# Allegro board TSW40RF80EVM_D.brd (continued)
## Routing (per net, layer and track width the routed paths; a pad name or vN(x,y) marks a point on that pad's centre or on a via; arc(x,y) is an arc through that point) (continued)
Net_259:
  vias: v1(148.69,18.54)
Net_261:
  vias: v1(148.69,14.73)
Net_262:
  vias: v1(148.69,13.46)
Net_263:
  vias: v1(148.69,10.92)
Net_267:
  vias: v1(147.42,38.86)
Net_268:
  vias: v1(147.42,57.91)
Net_271:
  vias: v1(147.42,28.7)
Net_273:
  vias: v1(147.42,24.89)
Net_275:
  vias: v1(147.42,21.08)
Net_276:
  vias: v1(147.42,19.81)
Net_278:
  vias: v1(147.42,16)
Net_279:
  vias: v1(147.42,13.46)
Net_282:
  vias: v1(147.42,9.65)
Net_297:
  vias: v1(146.15,21.08)
Net_298:
  vias: v1(146.15,18.54)
Net_300:
  vias: v1(146.15,14.73)
Net_301:
  vias: v1(146.15,13.46)
Net_315:
  vias: v1(144.88,16)
Net_318:
  vias: v1(144.88,9.65)
Net_350:
  vias: v1(142.34,35.05)
Net_361:
  vias: v1(142.34,13.46)
Net_362:
  vias: v1(142.34,12.19)
OSCI: length 5.5
  BOTTOM w0.305: U10.2 104.84,48.65 105.28,49.1 105.28,50.27 v1(107.04,52.02)
OSCINN: length 9.1
  BOTTOM w0.203: C228.2 46.62,35.23 C229.2 45.83,35.41 45.12,35.41 44.65,35.87 44.65,38.11 43.05,39.7 41.7,39.7 41.63,39.63 U7.44
OSCINP: length 9
  BOTTOM w0.203: U7.43 41.63,40.13 41.7,40.06 43.2,40.06 45.01,38.25 45.01,36.02 45.26,35.76 45.88,35.76 C223.2 46.62,35.89 C221.2
OSCN: length 1.9
  BOTTOM w0.381: C227.2 49.1,35.23 R112.2 R116.1 47.86,35.25 C228.1
OSCO: length 5.5
  BOTTOM w0.305: v1(107.85,49.79) 107.85,48.77 107.54,48.46 105.71,48.46 105.41,48.16 U10.3
OSCOUTN: length 5.3
  BOTTOM w0.203: U7.41 41.63,41.13 41.7,41.21 43.8,41.21 44.04,41.45 45.09,41.45 R121.1 45.85,41.3 C231.1
OSCOUTP: length 5.3
  BOTTOM w0.203: C230.1 45.85,41.96 R120.1 45.09,41.81 43.9,41.81 43.65,41.56 41.7,41.56 41.63,41.63 U7.40
OSCP: length 1.9
  BOTTOM w0.381: C221.1 47.86,35.86 R109.1 R104.2 49.1,35.89 C220.2
PDN: length 42.4
  TOP w0.127: JP4.2 65.49,37.2 v1(51.6,37.2) ; v1(45.8,50.8) 45.29,51.31 38.86,51.31 38.29,51.88 U2.50
  L4_SIG w0.127: v1(45.8,50.8) 45.8,49.85 48.33,47.32 48.51,47.32 52.43,43.4 52.43,38.02 v1(51.6,37.2)
PG_C2M: length 7.4
  L6_SIG w0.127: v1(155.68,57.28) 155.68,57.91 153.8,59.79 150.57,59.79 v1(149.96,59.18)
PG_M2C: length 9.4
  L6_SIG w0.127: v1(155.68,61.09) 155.27,61.49 150.83,61.49 149.22,59.89 148.03,59.89 147.42,59.28 v1(147.42,59.18)
PLL2 LOCKED: length 1.1
  TOP w0.127: R127.1 47.32,39.78 D5.1
PRSNT_M2C_L: length 17
  L4_SIG w0.127: v2(144.35,57.33) 145.29,58.27 145.29,58.32 145.57,58.6 149.91,58.6 155.68,52.83 v1(155.68,50.93)
  BOTTOM w0.102: J14.H2 144.88,57.86 v2(144.35,57.33)
RES0: length 4.5
  L8_SIG w0.127: v1(152.5,9.65) v1(155.68,6.48)
RX0N: length 13.4
  TOP w0.203: U1.M4 20.47,29.05 20.47,30.08 20.73,30.33 20.98,30.33 21.1,30.22 21.35,30.22 21.53,30.39 21.53,30.65 21.41,30.76 21.41,31.02 22.07,31.67 31.17,31.67 C18.2
RX0P: length 13.4
  TOP w0.203: U1.M5 20.12,29.14 20.12,30.23 21.92,32.03 31.17,32.03 C19.2
RX1N: length 10.8
  TOP w0.203: U1.M3 21.67,29.08 21.67,29.59 22.48,30.4 31.17,30.4 C22.2
RX1P: length 10.8
  TOP w0.203: U1.M2 22.02,29.11 22.02,29.44 22.63,30.05 22.9,30.05 23.08,29.87 23.08,29.72 23.25,29.54 23.51,29.54 23.68,29.72 23.68,29.87 23.86,30.05 31.17,30.05 C20.2
RX2N: length 8.4
  TOP w0.203: C23.2 31.17,28.42 26.89,28.42 26.77,28.3 23.28,28.3 U1.L1
RX2P: length 8.4
  TOP w0.203: U1.M1 23.28,28.65 26.62,28.65 26.75,28.78 31.17,28.78 C21.2
RX3N: length 8.5
  TOP w0.203: U1.K1 23.3,27.03 27.13,27.03 27.3,27.2 31.17,27.2 C24.2
RX3P: length 8.4
  TOP w0.203: C25.2 31.17,26.85 27.45,26.85 27.27,26.67 23.25,26.67 U1.J1
RX4N: length 8.4
  TOP w0.203: C15.2 31.17,23.95 27.41,23.95 27.3,23.85 23.28,23.85 U1.F1
RX4P: length 8.4
  TOP w0.203: U1.E1 23.28,23.5 27.45,23.5 27.55,23.6 31.17,23.6 C14.2
RX5N: length 8.4
  TOP w0.203: U1.B1 23.25,20.68 31.14,20.68 C10.2
RX5P: length 8.4
  TOP w0.203: C11.2 31.19,20.32 23.3,20.32 U1.A1
RX6N: length 8.4
  TOP w0.203: U1.C1 23.28,21.89 28.29,21.89 28.37,21.97 31.17,21.97 C12.2
RX6P: length 8.4
  TOP w0.203: U1.D1 23.28,22.25 28.14,22.25 28.22,22.33 31.17,22.33 C13.2
RX7N: length 8.4
  TOP w0.203: U1.G1 23.28,25.1 29.31,25.1 29.41,25.2 31.19,25.2 C17.2
RX7P: length 8.4
  TOP w0.203: C16.2 31.14,25.55 29.26,25.55 29.16,25.45 23.28,25.45 U1.H1
SCAN_EN: length 0.1
  BOTTOM w0.203: v3(37.79,53.65) 37.8,53.65 R50.2
SCL: length 16.1
  L6_SIG w0.127: v1(155.68,35.69) 155.68,33.83 155.22,33.38 155.22,26.97 151.41,23.16 150.67,23.16 v2(150.62,23.11)
  BOTTOM w0.102: J14.C30 150.62,22.96 v2(150.62,23.11)
SCLK: length 60.4
  L8_SIG w0.102: 15.47,29.22 15.47,28.7 15.7,28.47 16.25,28.47 v1(16.65,28.07)
  L8_SIG w0.127: v1(68.76,37.41) 68.73,37.67 67.46,38.94 43.33,38.94 41.99,37.59 29.51,37.59 26.92,35 26.59,35 24.82,33.22 18.77,33.22 15.47,29.92 15.47,29.22
SDA: length 9.7
  L8_SIG w0.127: v1(155.68,28.7) 155.68,25.7 152.17,22.2 151.69,22.2 151.23,21.74 v1(151.23,21.08)
SDCLKOUT3N: length 3.2
  BOTTOM w0.203: R75.1 29.31,43.79 R80.1 29.34,43.81 29.51,43.64 29.87,43.64 30.29,44.06 30.73,44.06 30.8,44.14 U7.14
SDCLKOUT3P: length 3.2
  BOTTOM w0.203: R74.1 29.31,43.18 R79.1 29.46,43.28 30.01,43.28 30.44,43.71 30.73,43.71 30.8,43.63 U7.13
SDCLKOUT5N: length 3.4
  BOTTOM w0.203: U7.23 35.46,46.8 35.39,46.87 35.39,47.36 35.08,47.67 35.08,48.22 R101.1 35.22,49.09 R99.1
SDCLKOUT5P: length 3.4
  BOTTOM w0.203: R96.1 34.53,49.1 R100.1 34.72,48.15 34.72,47.52 35.03,47.21 35.03,46.87 34.96,46.8 U7.22
SDENB: length 55.1
  L8_SIG w0.102: 17.81,29.22 17.47,28.87 v1(17.45,28.87)
  L8_SIG w0.127: v1(68.73,34.14) 67.44,32.84 66.4,32.84 65.41,33.83 41.23,33.83 41.17,33.9 37.59,33.9 37.52,33.83 35.23,33.83 34.32,34.75 33.4,34.75 30.3,31.65 24.97,31.65 23.27,29.95 18.97,29.95 18.44,29.41 18.01,29.41 17.81,29.22
SDIO: length 57.4
  L8_SIG w0.102: 15.85,29.22 v1(15.85,28.87)
  L8_SIG w0.127: v1(68.76,36.32) 68.22,36.86 59.16,36.86 58.22,35.92 45.19,35.92 44.98,36.12 37.52,36.12 36.83,36.8 33.32,36.8 32.61,36.09 32.41,36.09 28.98,32.66 19.25,32.66 15.85,29.27 15.85,29.22
SDO: length 56.2
  L8_SIG w0.102: 17,29.22 v1(16.65,28.87)
  L8_SIG w0.127: 17,29.22 17.64,29.86 18.09,29.86 18.64,30.4 22.71,30.4 24.49,32.18 29.26,32.18 31.94,34.86 32.73,34.86 33.17,35.31 34.32,35.31 35.38,34.24 37.85,34.24 38.94,35.33 59.33,35.33 59.54,35.53 61.7,35.53 62,35.23 65.81,35.23 66.22,34.82 68.3,34.82 v1(68.73,35.26)
SLEEP: length 93.9
  L6_SIG w0.127: JP1.2 73.84,12.57 72.14,10.87 57.61,10.87 57.15,10.41 38,10.41 37.72,10.13 23.6,10.13 21.82,11.91 17.81,11.91 14.02,15.7 13.06,15.7 9.47,19.28 9.47,28.25 11.76,30.53 v1(11.76,30.78)
  BOTTOM w0.102: 17.07,29.22 17.07,28.4 17.39,28.07 v1(17.45,28.07)
  BOTTOM w0.127: v1(11.76,30.78) 15.88,30.78 17.07,29.59 17.07,29.22
STAT 0: length 1.1
  TOP w0.127: R124.1 D2.1
STAT 1: length 1.1
  TOP w0.127: R125.1 D3.1
SYNC: length 1.1
  TOP w0.305: v3(31.27,40.13) v3(31.96,40.13)
  BOTTOM w0.305: U7.6 v3(31.27,40.13)
SYSREF-N: length 3.5
  TOP w0.203: U1.A4 20.88,19.85 20.88,16.86 R17.2
SYSREF-P: length 3.5
  TOP w0.203: U1.A3 21.23,19.85 21.23,16.87 R16.2
TCK: length 27.2
  L6_SIG w0.127: v1(149.96,23.62) 150.59,23.62 154.74,27.77 154.74,35.56 155.23,36.06 155.23,41.59 156.13,42.49 156.13,47.29 v1(155.68,47.75)
TDI: length 27.7
  L6_SIG w0.127: v2(149.33,21.59) 148.03,22.89 148.03,27.41 150.6,29.97 150.6,30.18 151.92,31.5 151.92,37.65 152.95,38.68 152.95,39.31 154.56,40.92 154.56,41.76 155.68,42.88 v1(155.68,44.58)
  BOTTOM w0.102: J14.D30 149.96,22.23 v2(149.33,21.59)
TDO: length 24.5
  L6_SIG w0.127: v1(149.96,21.08) 149.99,21.08 150.65,20.42 152.81,20.42 153.14,20.75 153.14,23.42 156.26,26.54 156.26,35.97 155.68,36.55 v1(155.68,40.13)
TMS: length 9.1
  L8_SIG w0.127: v1(149.96,18.54) 150.6,18.54 155.68,23.62 v1(155.68,24.89)
TRST_L: length 7.2
  L8_SIG w0.127: v1(155.68,14.73) 155.02,15.39 151.92,15.39 v2(151.89,15.37)
  BOTTOM w0.102: v2(151.89,15.37) 151.87,15.34 151.21,15.34 150.75,15.8 150.75,16.03 149.96,16.81 J14.D34
TXA0_M: length 5.3
  TOP w0.203: U2.62 41.03,57.71 43.13,57.71 44.55,59.13 45.39,59.13 C111.1
TXA0_P: length 5.2
  TOP w0.203: U2.61 41,57.35 43.28,57.35 44.7,58.78 45.39,58.78 C110.1
TXA1_M: length 5.2
  TOP w0.203: C124.1 45.39,57.51 44.81,57.51 43.52,56.21 41.03,56.21 U2.59
TXA1_P: length 5.2
  TOP w0.203: C123.1 45.39,57.15 44.96,57.15 43.66,55.85 41,55.85 U2.58
TXA2_M: length 5.1
  TOP w0.203: C126.1 45.39,55.88 44.91,55.88 43.77,54.74 41,54.74 U2.56
TXA2_P: length 5.1
  TOP w0.203: U2.55 41.03,54.38 43.92,54.38 45.06,55.52 45.39,55.52 C125.1
TXA3_M: length 7.2
  TOP w0.203: C135.1 45.34,54.13 44.99,54.13 43.62,52.76 42.1,52.76 41.92,52.93 41.92,53.06 41.74,53.24 41.49,53.24 41.31,53.06 41.31,52.93 41.13,52.76 40.54,52.76 40.21,53.09 40.21,53.56 U2.54
TXA3_P: length 7.2
  TOP w0.203: U2.53 39.85,53.59 39.85,52.94 40.39,52.4 43.76,52.4 45.14,53.77 45.44,53.77 C127.1
TXB0_M: length 5.1
  TOP w0.203: C137.1 45.39,60.4 44.07,60.4 43.03,59.36 41.01,59.36 U2.65
TXB0_P: length 5.1
  TOP w0.203: U2.66 41.02,59.72 42.88,59.72 43.92,60.76 45.39,60.76 C136.1
TXB1_M: length 5.1
  TOP w0.203: U2.68 41.03,60.88 42.62,60.88 43.76,62.03 45.39,62.03 C140.1
TXB1_P: length 5.1
  TOP w0.203: C138.1 45.39,62.38 43.61,62.38 42.47,61.24 41,61.24 U2.69
TXB2_M: length 5.2
  TOP w0.203: U2.71 41,62.36 41.6,62.36 42.9,63.65 45.39,63.65 C148.1
TXB2_P: length 5.2
  TOP w0.203: C141.1 45.39,64.01 42.75,64.01 41.45,62.71 41.03,62.71 U2.72
TXB3_M: length 7
  TOP w0.203: U2.1 40.22,63.52 40.22,64 40.58,64.36 40.83,64.36 40.94,64.25 41.19,64.25 41.37,64.43 41.37,64.68 41.26,64.79 41.26,65.04 41.5,65.28 45.39,65.28 C150.1
TXB3_P: length 7
  TOP w0.203: U2.2 39.87,63.52 39.87,64.14 41.36,65.63 45.39,65.63 C149.1
TXENABLE: length 103.2
  L6_SIG w0.127: v1(11.05,31.39) 11.05,31.29 8.94,29.18 8.94,19.15 12.14,15.95 12.14,15.37 15.57,11.94 16.26,11.94 17.35,10.85 20.98,10.85 23.93,7.9 29.69,7.9 30.71,8.92 58.95,8.92 59.89,9.86 62.56,9.86 62.56,9.88 62.84,10.16 63.2,10.16 63.47,9.88 63.47,9.86 73.08,9.86 74.78,11.56 80.37,11.56 JP2.2
  BOTTOM w0.102: v1(19.05,27.27) 19.05,27.35 18.64,27.77 18.64,28.3 18.44,28.5 18.1,28.5 17.88,28.72 17.88,29.22
  BOTTOM w0.127: 17.88,29.22 17.88,29.39 16.1,31.17 13.51,31.17 13.28,31.39 v1(11.05,31.39)
USB_DM: length 45.4
  BOTTOM w0.203: R139.2 135.36,20.73 C267.1 135.38,21.14 135.22,21.3 135.22,24.72 134.34,25.6 133.88,25.6 127.28,32.21 124.84,32.21 115.64,41.4 115.37,41.4 112.65,44.12 109.14,44.12 107.49,45.77 105.66,45.77 105.35,46.08 104.7,46.08 104.62,46.16 U10.7
USB_DP: length 45.4
  BOTTOM w0.203: U10.8 104.56,45.65 104.62,45.72 105.21,45.72 105.51,45.42 107.34,45.42 108.99,43.76 112.5,43.76 115.22,41.05 115.49,41.05 124.69,31.85 127.13,31.85 133.74,25.25 134.19,25.25 134.86,24.57 134.86,24.32 134.68,24.14 134.54,24.14 134.37,23.96 134.37,23.71 134.54,23.53 134.68,23.53 134.86,23.35 134.86,21.3 134.7,21.14 C266.1 134.72,20.73 R142.2
USB_EECLK: length 5.1
  TOP w0.127: R156.1 100.77,51.8 v3(100.77,51.03) 100.77,49.66 99.52,48.42 U12.2
USB_EECS: length 5
  TOP w0.127: v3(101.27,51.88) 101.27,51.87 101.27,49.56 100.17,48.46 U12.1
USB_REF:
  vias: v3(102.79,46.65)
USB_RST:
  vias: v3(104.5,42.66)
VCM: length 17.9
  TOP w0.203: v1(30.53,61.32) 30.55,61.3 U2.22
  L4_SIG w0.203: v1(30.53,61.32) 30.53,61.85 29.46,62.92 26.95,62.92 26.62,62.59 16.74,62.59 v1(16.59,62.43)
  BOTTOM w0.305: TP5.1 14.61,62.43 v1(16.59,62.43)
VIO_B_M2C: length 17.8
  L8_SIG w0.127: v1(143.61,10.92) v1(142.34,9.65) 142.37,9.65 143.41,8.61 150.37,8.61 v1(155.68,3.3)
VREF_A_M2C: length 13.3
  L4_SIG w0.127: v1(155.68,54.1) 150.14,59.64 145.34,59.64 v1(144.88,59.18)
VREF_B_M2C: length 16.2
  L6_SIG w0.127: v1(144.27,59.74) 144.22,59.79 144.22,60.5 147.6,63.88 155.3,63.88 v1(155.68,64.26)
  BOTTOM w0.102: 142.72,59.56 J14.K1
  BOTTOM w0.127: v1(144.27,59.74) 144.02,59.99 143.15,59.99 142.72,59.56
Y2_N: length 4.8
  BOTTOM w0.381: Y1.4 53.26,34.32 52.35,35.23 R114.1 51.03,35.23 R113.1
Y2_P: length 4.8
  BOTTOM w0.381: R107.1 51.03,35.89 R108.1 52.27,35.89 53.24,36.86 Y1.5
YO2_N: length 0.7
  BOTTOM w0.381: C227.1 R113.2
YO2_P: length 0.7
  BOTTOM w0.381: R107.2 C220.1
N16791764: length 3.1
  BOTTOM w0.254: R138.1 133.43,18.59 J15.1
N16791900:
  vias: v3(102.89,47.64) v3(103.64,47.65) v3(104.46,47.66)
N16791904: length 1.7
  TOP w0.305: v3(104.52,45.15) 103.63,45.15 C247.1 ; C247.1 103.55,45.18 102.92,45.18 C248.1 ; C247.1 103.59,45.2 v3(103.64,45.16)
  vias: v3(102.87,45.15)
N16792068: length 1.3
  TOP w0.127: R151.2 R146.2 R150.1
N16792392: length 2.3
  TOP w0.127: R157.1 98.24,49.43 R159.2 98.22,48.94 U12.4
N17033323:
  vias: v1(106.09,46.42)
N17033325: length 0.4
  BOTTOM w0.305: v1(107.46,46.43) 107.44,46.42 R137.2
N17828171: length 5.5
  BOTTOM w0.305: v1(111.35,47.9) 111.35,48.83 v1(111.36,48.83)
  BOTTOM w0.508: FB13.1 113.87,50.26 113.41,49.81 111.96,49.81 111.36,49.21 v1(111.36,48.83)
N17829143: length 1.1
  BOTTOM w0.305: R136.1 112.73,45.68 v1(113.28,46.24)
N17906763: length 4.7
  TOP w0.381: J13.1 28.35,43.51 28.73,43.13 28.73,41.66 R123.1
N18864728: length 0.4
  TOP w0.127: Q2.1 138.91,41.53 v1(138.89,41.5)
N18864763: length 12.6
  BOTTOM w0.102: 141.86,40.61 146.35,40.61 146.63,40.34 146.63,40.23 147.4,39.47 147.52,39.47 148.13,38.86 148.13,38.56 148.44,38.25 149.35,38.25 J14.D17
  BOTTOM w0.127: R132.1 141.07,40.49 141.2,40.61 141.86,40.61
N18864775: length 12.9
  TOP w0.127: v1(138.89,33.17) 139.06,33.35 142.77,33.35 146.18,36.75 149.1,36.75 v1(149.28,36.93)
  BOTTOM w0.102: v1(149.28,36.93) 149.3,36.93 J14.D18
N18864798: length 0.9
  TOP w0.127: v1(138.96,42.49) 139.29,42.82 Q2.3
N18865554:
  vias: v1(137.97,42.44)
N19080738:
  vias: v1(53.77,40.06) v1(54.48,40.21) v1(55.12,40.21) v1(55.75,40.21) v1(56.39,40.21)
N19081029:
  vias: v1(60.4,36.09)
N19083254: length 8.8
  TOP w0.127: R126.2 45.21,44.73 42.16,47.78 40.51,47.78 v1(39.47,46.74)
  BOTTOM w0.127: U7.31 39.47,46.73 v1(39.47,46.74)
N19083268: length 8.3
  TOP w0.127: v1(41.78,37.03) 41.78,36.53 42.21,36.09 43.97,36.09 44.4,36.53 44.4,38.94 R127.2
  BOTTOM w0.127: v1(41.78,37.03) 41.19,37.63 U7.48
N19083286: length 13.8
  TOP w0.127: v1(34.95,35.31) 35.41,35.31 36.12,36.02 36.12,36.22 37.41,37.52 38.28,37.52 40.39,35.41 45.14,35.41 R125.2
  BOTTOM w0.127: U7.59 34.96,35.32 v1(34.95,35.31)
N19083328: length 15.3
  TOP w0.127: v1(35.46,35.99) 35.46,36.58 36.7,37.82 36.7,38.18 37.15,38.63 38.48,38.63 38.73,38.38 38.73,37.62 40.59,35.76 44.37,35.76 45.21,36.6 45.21,37.62 R124.2
  BOTTOM w0.127: U7.58 35.46,36 v1(35.46,35.99)
N19083344: length 0.3
  BOTTOM w0.305: U7.12 31.97,43.13 v3(31.98,43.13)
N19083346: length 0.5
  BOTTOM w0.305: v3(31.14,42.65) 31.15,42.63 U7.11
N19083364: length 1.5
  TOP w0.305: v3(31.63,42.13) 31.65,42.11 C232.2
  BOTTOM w0.305: v3(31.98,42.14) 31.97,42.13 v3(31.63,42.13) ; v3(40.44,45.13) 40.44,45.14 U7.33 41.12,45.14 v3(41.22,45.24)
  vias: v3(40.44,43.64)
N19083444: length 1.6
  TOP w0.305: FB7.2 40.48,42.11 v3(40.46,42.13) v3(41.12,42.13)
  BOTTOM w0.305: U7.39 v3(40.46,42.13)
N19083446: length 0.6
  TOP w0.305: FB9.2 40.47,39.14 v3(40.46,39.13)
  vias: v3(41.12,39.14)
N19083508: length 4.4
  TOP w0.305: 42.04,39.14 42.04,39.09 v3(41.07,38.13) v3(40.46,38.13) ; v1(41.81,38.13) 42.04,38.13 42.65,38.73 FB6.2
  BOTTOM w0.305: v1(41.81,38.13) 41.8,38.13 U7.47
N19083566: length 1.4
  TOP w0.305: v3(34.47,45.62) 34.47,46.29 v3(34.46,46.29) ; C236.2 FB3.2
N19083568: length 1.4
  TOP w0.305: v3(32.46,45.63) 32.46,46.3 v3(32.46,46.3) ; C235.2 FB5.2
N19083616: length 4.5
  TOP w0.305: 32.46,37.11 v4(32.46,36.45) ; 32.46,37.11 v4(32.46,37.13) 32.03,36.32 ; 32.46,37.11 32.09,36.74 ; v4(32.46,36.45) 32.46,36.35 C244.2 32.09,36.66 32.09,36.74 ; v4(32.46,36.45) 32.33,36.32 ; 32.09,36.74 31.67,36.32
  TOP w0.508: FB11.2 31.67,36.32 C244.2
N19083618: length 1.1
  TOP w0.305: C243.2 FB10.2
  BOTTOM w0.305: U7.53 v3(37.96,37.13)
  vias: v3(37.96,36.47)
N19083707: length 1.6
  TOP w0.305: FB4.2 37.03,46.29 ; 37.03,46.29 v3(36.96,46.29) 36.96,45.71 C237.2 ; 37.03,46.29 C237.2 ; C237.2 v3(36.96,45.64)
N19234861: length 0.6
  TOP w0.305: v3(40.46,40.63) 40.48,40.61 FB8.2
  vias: v3(41.12,40.64)
N19402254: length 1.6
  L4_SIG w0.102: v3(96.95,49.56) 96.77,49.74 v3(96.77,51.03)
N19402263: length 1.5
  L4_SIG w0.102: v3(96.27,51.03) 96.27,49.63 v3(96.19,49.56)
N19402272: length 1.6
  L4_SIG w0.102: v3(95.77,51.03) 95.77,49.84 v3(95.48,49.56)
N19402281: length 0.9
  BOTTOM w0.127: U10.48 93.22,49.16 v3(93.24,49.17)
N19909006: length 1.5
  TOP w0.305: C290.2 91.22,14.7 U17.8
N20060120: length 3.2
  TOP w0.203: C9.1 18.82,17.2 18.82,19.84 U1.A6
N20060672: length 3.2
  TOP w0.203: U1.A7 18.49,19.84 18.49,17.22 C7.1
N20072726: length 1.9
  TOP w0.305: C427.1 R228.2 28.37,59.37 28.07,59.67 U3.6
N20072730: length 2
  TOP w0.305: U4.6 28.07,57.34 28.37,57.64 R228.1 C428.1
N20074990: length 2.6
  TOP w0.381: C166.2 18.45,64.14 T6.4 R57.1
N20074992: length 3.5
  TOP w0.381: R56.1 T6.6 18.45,66.93 C165.2 C164.2
N20075215: length 2.6
  TOP w0.381: R54.1 T4.6 18.45,52.96 C159.2
N20075219: length 3.4
  TOP w0.381: R55.1 T4.4 18.43,50.14 C161.2 C160.2
N20076572: length 1.1
  TOP w0.127: R64.1 D1.1
N20076618:
  vias: v3(71.07,51.05) v3(71.07,50.34)
N20076637: length 0.9
  TOP w0.305: v3(72,47.43) 72.09,47.51 C188.2 U5.36 v3(72.64,47.43)
N20076686: length 0.3
  TOP w0.305: C191.2 72.36,48.95 v3(72.39,48.92)
  vias: v3(72.01,48.92)
N20076744: length 2.6
  BOTTOM w0.203: U5.23 68,50.77 68,52.31 R58.1 68.19,53.11 C170.1
N20076746: length 2.5
  BOTTOM w0.203: U5.22 67.67,50.81 67.67,52.37 R59.1 67.56,52.53 C171.1
N20076858:
  vias: v3(67.06,44.3)
N20076866: length 4.9
  BOTTOM w0.203: C181.1 63.24,51.05 R61.1 63.42,51.01 64.03,50.4 64.03,49.96 65,48.99 65.53,48.99 65.53,49 66.22,49 U5.18
N20076868: length 4.6
  BOTTOM w0.203: C184.1 63.67,51.48 R62.1 63.7,51.23 64.39,50.55 64.39,50.11 65.15,49.35 65.15,49.35 66.21,49.35 U5.19
N20076920: length 0.6
  BOTTOM w0.305: C193.2 R70.1
N20076959: length 1.2
  BOTTOM w0.305: R69.1 C194.1 R68.2
N20076978: length 1.9
  BOTTOM w0.305: R69.2 72.34,47.93 U5.35 72.77,47.93 v3(72.8,47.9)
N20077010: length 0.3
  BOTTOM w0.305: U5.30 71.78,50.7 v3(71.84,50.63)
N20077268: length 0.7
  BOTTOM w0.305: v3(70.08,50.37) 70.06,50.39 U5.27 70.06,51.05 v3(70.05,51.05)
N20077503: length 8
  L6_SIG w0.127: v3(66.29,49.93) 66.81,49.4 67.23,49.4 68.02,50.19 69.14,50.19 69.31,50.03 70.22,50.03 70.89,50.7 71.3,50.7 71.58,50.98 72.62,50.98 v1(73.1,50.5)
N20087628: length 5
  L6_SIG w0.102: 13.92,22.07 16.25,22.07 v3(16.65,21.67)
  L6_SIG w0.127: 13.92,22.07 13.41,22.07 v3(12.27,20.93)
N20088284: length 1.7
  TOP w0.381: R23.2 R24.1 10.84,21.99 11.43,22.58
N20088327: length 1.7
  TOP w0.381: R20.2 R21.1 C26.2
N20098160:
  vias: v3(103.87,41.65)
N20098174: length 1.6
  TOP w0.305: U31.19 89.71,38.58 R326.2
  vias: v3(88.32,38.58)
N20098233:
  vias: v3(101.77,40.62)
N20098235:
  vias: v3(101.27,39.78)
N20098237:
  vias: v3(100.76,38.96)
N20101383: length 7.6
  L6_SIG w0.127: v3(95.76,41.24) 95.76,41.35 93.95,43.16 v3(88.99,43.16)
N20101387: length 9.6
  L10_PWR_SIG w0.102: v3(96.26,38.32) 96.26,38.36 95.05,39.57 95.05,39.9 91.9,43.05 89.38,43.05 v3(88.99,42.66)
N20101391: length 8.4
  L6_SIG w0.127: v3(96.75,41.26) 96.43,40.94 93.65,40.94 92.43,42.16 v3(88.99,42.16)
N20101395: length 10.7
  L10_PWR_SIG w0.102: v3(88.11,41.07) 91.03,41.07 92.91,39.19 93.47,39.19 94.82,37.85 96.81,37.85 v3(97.28,38.32)
N20101461: length 3.6
  BOTTOM w0.127: U11.12 89.61,45.16 90.1,45.65 U10.41
N20101463: length 3.6
  BOTTOM w0.127: U10.40 90.47,45.16 89.99,44.68 89,44.68 U11.13
N20101465: length 3.6
  BOTTOM w0.127: U10.39 90.58,44.65 90.08,44.16 U11.14
N20101467: length 3.6
  BOTTOM w0.127: U11.15 90.37,43.66 90.87,44.16 U10.38
N20101487:
  vias: v3(94.28,38.93)
N20101489:
  vias: v3(95.27,38.93)
N20101501:
  vias: v3(96.75,40.66)
N20101503:
  vias: v3(95.76,40.63)
N20101505:
  vias: v3(97.28,38.93)
N20101507:
  vias: v3(96.26,38.93)
N20119510: length 1.7
  BOTTOM w0.305: U15.7 44.19,5.2 44.69,5.7 C282.1
N20119513: length 1.9
  BOTTOM w0.305: C282.2 45.71,5.78 45.72,5.77 U15.8
N20119835: length 1.7
  BOTTOM w0.305: C283.1 43.69,1.73 U15.3
N20120157: length 2.9
  BOTTOM w0.305: R161.1 R163.1 42.16,6.07 42.16,5.97 43.19,4.94 U15.5
N20121909: length 2.8
  TOP w0.305: R169.1 v1(92.86,13.44) R168.1
  BOTTOM w0.305: v1(92.6,15.35) 92.6,14.28 92.86,14.02 v1(92.86,13.44)
N20122091: length 2
  TOP w0.305: R339.1 R338.1 94.84,14.66 U17.1
  vias: v1(94.79,14.66)
N20123661: length 1.5
  BOTTOM w0.127: R362.2 86.41,10.9 C294.2
N20123671: length 3.3
  L8_SIG w0.305: v1(90.14,11.51) 90.63,11.02 90.81,11.02 91.29,10.54 91.29,9.57 v1(90.74,9.02)
N20123702: length 4.1
  TOP w0.305: v1(88.54,9.67) 88.54,10.56 88.93,10.95 88.93,12.22 v1(89.23,12.52)
  BOTTOM w0.305: v1(89.23,12.52) R171.1
N20123718: length 4.8
  TOP w0.305: v1(90.74,10.32) 90.54,10.32 89.56,11.3 89.56,11.79 90.3,12.52 v1(91.06,12.52)
  BOTTOM w0.305: R336.1 v1(91.06,12.52)
N20149572: length 7.8
  L4_SIG w0.127: v3(98.27,51.03) 98.27,46.9 96.55,45.19 95.83,45.19 v3(95.48,45.54)
N20149573: length 4.5
  L4_SIG w0.127: v3(93.24,52.27) 96.02,52.27 v3(97.27,51.03)
N20149574: length 7
  TOP w0.127: v3(96.19,45.54) 97.33,46.69 97.33,50.32 97.66,50.65 98.42,50.65 98.77,50.99 v3(98.77,51.03)
N20149575:
  vias: v3(99.26,51.87)
N20165749: length 12.7
  BOTTOM w0.203: L18.1 C445.2 26.76,52.7 28.27,51.19 34.91,51.19 35.24,50.86 35.52,50.86 35.85,51.19 36.26,51.19 36.64,50.81 36.64,50.4 C207.2
N20165751: length 12.7
  BOTTOM w0.203: C208.2 37,50.37 37,50.95 36.4,51.55 28.41,51.55 26.97,52.99 C446.2 26.48,53.83 L19.1
N20264121: length 1.9
  TOP w1.016: FB1.1 50.91,40.06 JP6.1
N20275382: length 1.6
  TOP w0.381: U24.8 117.82,43.19 C366.2
N20275455: length 2
  TOP w0.381: U24.3 119.12,38.06 L10.2
N20275475: length 3.9
  TOP w0.381: v1(115.62,42.01) R200.1
  L4_SIG w0.127: v1(115.62,42.01) 118.12,42.01 v1(118.47,41.66)
N20275808: length 1.6
  TOP w0.381: U25.8 132.65,43.14 C376.2
N20275812: length 6.9
  TOP w0.381: U25.3 133.95,38.16 L11.2
  L10_PWR_SIG w0.127: v1(130.43,40.26) 131.72,38.96 134.19,38.96 134.6,39.38 v1(134.6,39.44)
N20275835: length 4
  TOP w0.381: v1(130.43,42.09) R203.1
  L4_SIG w0.127: v1(130.43,42.09) 132.85,42.09 v1(133.3,41.64)
N20276430: length 1.5
  TOP w0.381: C380.2 125.19,43.19 U26.8
N20276599: length 7.1
  TOP w0.381: U26.3 126.49,38.21 L12.2
  L10_PWR_SIG w0.127: v1(122.99,40.31) 124.43,38.86 126.59,38.86 127.14,39.41 v1(127.14,39.51)
N20276622: length 3.9
  TOP w0.381: R206.1 v1(122.99,42.14)
  L4_SIG w0.127: v1(122.99,42.14) 125.41,42.14 v1(125.84,41.71)
N20277804: length 19.1
  L3_PWR_SIG w0.127: v1(133.3,39.44) 132.63,38.76 126.72,38.76 125.97,39.51 v1(125.84,39.51) 125.82,39.51 125.2,38.89 116.92,38.89 v1(115.62,40.18)
N20277812: length 2.2
  TOP w0.381: R207.1 R208.1 116.83,39.46 U24.1
N20277928: length 2.2
  TOP w0.381: U25.1 131.54,39.44 131.44,39.34 131.44,40.26
N20285160:
  vias: v1(104.04,37.47) v1(104.06,38.61) v1(105.33,38.61) v1(105.31,37.47) v1(106.48,38.61) v1(106.45,37.47) v1(107.52,38.61) v1(107.49,37.47)
N20285162: length 0.7
  TOP w0.305: v3(112.34,39.34) 112.37,39.37 C348.1 112.95,39.37 v3(112.98,39.34)
N20285184: length 1.3
  BOTTOM w0.305: v1(113.94,40.11) 113.82,39.98 U22.13
N20285196: length 0.8
  TOP w0.305: v3(112.37,40.64) 112.45,40.56 R188.2 112.83,40.49 v3(112.98,40.64)
N20285198: length 0.6
  TOP w0.305: v3(112.98,41.27) 112.85,41.4 R189.2
  vias: v3(112.37,41.27)
N20285293: length 0.7
  TOP w0.305: v3(111.61,42.7) 111.46,42.55 R190.2 111.46,42.21 v3(111.58,42.09)
N20285833:
  vias: v1(123.19,15.88) v1(123.19,14.61) v1(123.19,13.34) v1(123.19,12.06) v1(123.19,10.79) v1(123.19,8.89) v1(123.19,7.62) v1(123.32,6.1) v1(124.46,15.24) v1(124.46,13.97) v1(124.46,12.7) v1(124.46,11.43) v1(124.46,10.16) v1(124.46,8.89) v1(124.46,7.62) v1(124.46,6.35) v1(125.73,15.24) v1(125.73,13.97) v1(125.73,12.7) v1(125.73,11.43) v1(125.73,10.16) v1(125.73,8.89) v1(125.73,7.62) v1(125.73,6.35) v1(127,15.88) v1(127,14.61) v1(127,13.34) v1(127,12.06) v1(127,8.89) v1(127,7.62) v1(127,6.35) v1(128.27,8.89) v1(128.27,7.62) v1(128.27,6.35)
N20285975: length 3
  BOTTOM w0.508: v1(127.94,10.36) 129.46,11.88 U14.4
N20288221: length 2.1
  TOP w0.381: U26.1 124.12,39.51 R212.1 R211.1
N20326292: length 1.3
  TOP w0.127: v3(84.56,42.93) 85.29,43.66 v3(85.58,43.66)
N20326294: length 2.5
  TOP w0.102: 85.39,44.16 v3(85.58,44.16)
  TOP w0.127: v3(83.62,42.9) 84.23,43.51 84.73,43.51 85.39,44.16 85.39,44.16
N20326306: length 2.6
  TOP w0.127: R306.2 83.95,45.54 84.85,45.54 v3(85.58,44.66)
N20326308: length 1.2
  BOTTOM w0.102: U11.9 85.39,45.16
  BOTTOM w0.127: 85.39,45.16 v3(84.58,45.16)
N20413661: length 2.6
  TOP w0.127: R52.2 30.02,62.79 PP29.1 ; R52.2 R51.2 ; R52.2 30.08,62.3 U2.20
N20413665: length 2.6
  TOP w0.127: PP30.1 29.39,61.34 R53.2 R52.1 30.07,61.8 U2.21
N20414446: length 4.5
  TOP w0.127: R47.1 97.05,6.38 99.69,3.73 SW2.1
N20417693: length 3.7
  TOP w0.381: C153.2 12.86,58.37 arc(12.94,58.8) 13.18,59.15 arc(13.46,59.34) 13.8,59.41 T3.6
N20417714:
  vias: v1(17.35,58.17)
N20426571: length 2.5
  BOTTOM w0.305: U15.6 43.69,6.07 R217.1 R218.1
N20426573: length 7.4
  L6_SIG w0.305: v1(43.84,7.24) 43.84,5.94 46.38,3.4 v1(46.38,2.69)
  BOTTOM w0.305: U15.1 44.93,2.69 v1(46.38,2.69)
N20442953: length 4
  TOP w0.305: R219.2 v1(110.74,11.07) R220.1
  BOTTOM w0.305: v1(110.74,11.07) 111.4,11.07 111.82,11.49 v1(113.59,11.49)
N20493705: length 0.8
  TOP w0.381: R83.2 R84.1
N20497118:
  vias: v3(99.77,40.21)
N20546375: length 0.4
  TOP w0.305: C189.2 72.21,46.3 v3(72.33,46.43)
N20546772: length 0.9
  BOTTOM w0.305: v1(70.56,43.71) 70.56,43.71 U5.3
N20549887: length 0.9
  BOTTOM w0.127: R363.1 R171.2
N20556233: length 63.7
  L4_SIG w0.102: v1(20.65,27.27) 21.04,27.66 23.34,27.66 23.43,27.74
  L4_SIG w0.127: J5.1 71.04,37.11 71.04,29.31 70.48,28.75 24.43,28.75 23.43,27.74
N20556256: length 68
  L4_SIG w0.102: v1(20.65,25.67) 20.67,25.67 21.06,26.06 23.04,26.06 23.43,25.67
  L4_SIG w0.127: J5.3 75.41,37.37 75.41,34.09 74.83,33.5 73.74,33.5 73.41,33.17 73.41,25.83 72.78,25.21 29.93,25.21 29.84,25.3 23.8,25.3 23.43,25.67
N20556281: length 61.8
  L4_SIG w0.102: 23.43,26.9 21.06,26.9 20.65,26.5 v1(20.65,26.47)
  L4_SIG w0.127: 23.43,26.9 29.54,26.9 29.57,26.92 71.58,26.92 72.31,27.66 72.31,34.38 J5.5
N20556364: length 58.2
  BOTTOM w0.102: 21.12,29.22 21.03,29.13 21.03,27.91 20.8,27.69 20.27,27.69 v1(19.85,27.27)
  BOTTOM w0.127: 21.12,29.22 22.17,30.28 70.21,30.28 J5.7
N20556495: length 67.2
  L4_SIG w0.102: 23.43,23.84 22.78,24.49 21.95,24.49 21.13,25.3 20.5,25.3 20.27,25.53 20.27,26.06 v1(19.85,26.47)
  L4_SIG w0.127: 23.43,23.84 23.55,23.72 29.87,23.72 29.96,23.63 73.11,23.63 74.68,25.2 74.68,32.11 J5.9
  BOTTOM w0.102: v1(19.85,26.47) 19.85,26.48 19.46,26.87 19.46,28.22 R239.1
N20643618: length 0.9
  TOP w0.254: U29.4 21.2,59.29 C429.2
N20643644: length 0.8
  TOP w0.254: C430.2 21.17,56.95 U30.4
N20643698: length 0.7
  TOP w0.254: C431.2 23.88,59.28 U27.3
N20643721: length 0.7
  TOP w0.254: C432.2 23.95,56.97 U28.3
N20643769: length 0.7
  TOP w0.254: C433.2 26.51,60.67 U3.3
N20643792: length 0.7
  TOP w0.254: U4.3 26.54,58.34 C434.2
N20651473: length 16.3
  L6_SIG w0.127: v1(128.02,13.34) 129.18,12.17 137.92,12.17 142.09,8 v1(142.11,8)
N20670192: length 18.5
  TOP w0.127: R319.2 104.5,41.07 v1(104.52,41.05)
  L8_SIG w0.127: v1(104.52,41.05) 104.51,41.06 100.06,41.06 99.72,40.72 97.18,40.72 96.96,40.93 89.4,40.93 v3(87.63,39.17)
N20670214: length 15.2
  L8_SIG w0.127: v1(102.39,40.61) 102.08,40.31 100.66,40.31 100.16,39.81 95.77,39.81 95.38,40.21 93.17,40.21 92.23,39.27 89.71,39.27 v3(88.52,38.08)
N20670236: length 15.9
  TOP w0.127: R314.1 v1(102.62,39.07)
  L8_SIG w0.127: v3(88.52,37.58) 88.69,37.58 89.89,38.79 93.9,38.79 94.07,38.62 101,38.62 101.45,39.07 v1(102.62,39.07)
N20670258: length 14
  TOP w0.127: R317.2 v1(101.37,38.35)
  L8_SIG w0.127: v3(88.52,37.08) 88.65,37.21 100.23,37.21 v1(101.37,38.35)
N20674238: length 0.4
  TOP w0.127: v1(138.89,34.19) Q1.1
N20674280:
  vias: v1(137.97,35.43)
N20698575: length 15.4
  TOP w0.127: R330.1 99.47,40.82 v1(99.11,41.17)
  BOTTOM w0.127: v1(99.11,41.17) 99.11,41.22 98.48,41.86 94.41,41.86 93.62,41.07 90.37,41.07 89.23,39.93 89.23,37.29 v3(88.52,36.58)
N20715968: length 0.1
  BOTTOM w0.102: v1(21.45,27.27) 21.38,27.35 21.38,27.38
N20730230: length 4.7
  TOP w0.305: 66.17,11 66.02,10.85 U21.17 U21.16 ; C318.1 69.82,9.57 U21.15
N20730282: length 2.8
  TOP w0.305: R354.1 69.9,8.59 R355.1 68.65,9.07 U21.14
N20730294: length 6.6
  TOP w0.305: U21.19 U21.20 ; U21.1 63.54,9.7 v1(63.02,9.7) C317.2
  BOTTOM w0.127: v1(59.56,7.75) 59.56,7.85 61.42,9.7 v1(63.02,9.7)
N20730354: length 3.7
  TOP w0.305: R256.1 R254.2 61.98,8.26 C317.1 62.09,8.57 U21.3
N20730369: length 1.8
  TOP w0.305: U21.7 65.02,6 v1(65.02,5.99)
  BOTTOM w0.305: v1(65.02,5.99) 65.02,6.15 65.56,6.68 R334.2
N20730383: length 0.8
  TOP w0.305: v1(64.21,6.73) 64.22,6.72 U21.6
  BOTTOM w0.305: v1(64.21,6.73) 64.29,6.81 R335.2
N20730407: length 1.7
  TOP w0.305: U21.5 63.67,7.1 v1(63.5,6.93)
  BOTTOM w0.305: R182.2 v1(63.5,6.93)
N20730507: length 2.7
  TOP w0.305: U21.2 62.89,9.07 v1(62.87,9.09)
  BOTTOM w0.305: v1(61.11,8.71) 61.49,9.09 v1(62.87,9.09)
N20730511: length 1.9
  TOP w0.127: R364.2 60.63,7.8 R254.1 ; R365.1 60.1,8.28 R180.1
N20730545: length 2
  TOP w0.305: C326.2 68.99,7.75 68.16,8.57 U21.13
N20737136: length 2.5
  TOP w0.305: 113.16,8.1 112.94,8.32 U23.1 112.9,9.25 R341.1
N176074941: length 0.7
  TOP w0.203: C202.2 R87.1
N176076570: length 0.7
  BOTTOM w0.305: C198.2 R76.1
N206742472: length 1.8
  TOP w0.127: Q1.3 140.08,35.18 v1(140.08,35.03)
  BOTTOM w0.127: R128.2 139.67,35.43 v1(140.08,35.03)

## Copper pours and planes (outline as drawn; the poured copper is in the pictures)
1.8V_USB on L3_PWR_SIG: 90.22,45.59 93.73,45.59 93.73,46.48 91.82,48.39 91.82,51.05 92.2,51.44 94.36,51.44 94.36,49.53 94.87,49.02 100.58,49.02 101.47,49.91 101.47,51.74 101.8,52.07 105.16,52.07 105.16,44.32 104.27,43.43 101.47,43.43 100.46,44.45 98.04,44.45 96.27,42.67 91.31,42.67 89.92,44.07 88.27,44.07 88.27,41.48 88.62,41.12 90.17,41.12 90.17,39.37 85.22,39.37 85.22,51.56 88.27,51.56 88.27,47.55
3.3V_USB on TOP: 90.25,47.45 90.25,45.97 93.4,45.97 93.4,47.45
3.3V_USB on BOTTOM: 109.45,52.58 109.45,50.22 110.87,50.22 110.87,52.58
3.3V_USB on L3_PWR_SIG: 79.88,37.85 79.88,55.24 111.38,55.24 111.38,49.28 108.58,46.48 108.58,43.18 102.97,37.57 101.07,37.57 95.89,32.38 85.34,32.38
5.0V_SOURCE on BOTTOM (solid shape): 133.57,6.2 129.76,6.2 129.76,10.72 133.57,10.72
5.0V_SOURCE on TOP: 123.83,0.38 123.83,4.45 124.97,5.59 129.64,5.59 129.64,10.77 132.72,10.77 132.72,6.35 134.62,4.45 136.53,4.45 136.53,0.38
5.0V_SOURCE on BOTTOM: 123.83,0.38 123.83,4.45 124.97,5.59 129.64,5.59 129.64,11.18 134.09,11.18 134.09,4.98 134.62,4.45 136.53,4.45 136.53,0.38
5.0V_SOURCE on L3_PWR_SIG: 123.83,0.38 123.83,4.45 124.97,5.59 129.64,5.59 129.64,10.82 132.72,10.82 132.72,6.35 134.62,4.45 136.53,4.45 136.53,0.38
5.0V_SOURCE on L4_SIG: 123.83,0.38 123.83,4.45 124.97,5.59 129.64,5.59 129.64,10.85 132.72,10.85 132.72,6.35 134.62,4.45 136.53,4.45 136.53,0.38
5.0V_SOURCE on L6_SIG, L8_SIG: 123.83,0.38 123.83,4.45 124.97,5.59 129.64,5.59 129.64,10.79 132.72,10.79 132.72,6.35 134.62,4.45 136.53,4.45 136.53,0.38
5.0V_SOURCE on L10_PWR_SIG: 123.83,0.38 123.83,4.45 124.97,5.59 128.35,5.59 129.64,6.88 129.64,10.85 132.72,10.85 132.72,6.35 134.62,4.45 136.53,4.45 136.53,0.38
+1.8V_ANA on TOP: 24.77,9.22 24.77,10.87 30.38,10.87 30.38,9.22
+1.8V_ANA on BOTTOM: 24.77,9.22 24.77,10.87 30.73,10.87 30.73,9.22
+1.8V_ANA on L3_PWR_SIG: 8.76,15.95 8.76,25.91 10.54,27.69 12.6,27.69 14.12,26.16 14.61,26.16 15.11,25.65 15.11,24.77 13.97,23.62 13.97,16.76 19.94,10.79 30.23,10.79 30.23,7.62 17.09,7.62
+1.8V_CLK on TOP: 26.16,13.28 26.16,14.86 33.4,14.86 33.4,13.28
+1.8V_CLK on BOTTOM: 26.21,13.21 26.21,14.86 36.07,14.86 36.07,12.45 33.66,12.45 32.89,13.21
+1.8V_CLK on L3_PWR_SIG: 15.62,16.66 20.75,11.53 32.44,11.53 32.44,14.86 22.43,14.86 18.47,18.81 18.47,20.98 18.08,21.36 15.62,21.36
+1.8V_DIG on TOP: 52.68,13.11 52.68,14.76 59.03,14.76 59.03,13.11
+1.8V_DIG on BOTTOM: 52.7,13.11 52.7,14.76 59.03,14.76 59.03,13.11
+1.8V_DIG on L10_PWR_SIG: 20.07,21.21 20.07,23.24 19.38,23.93 19.38,25.6 19.63,25.86 20.32,25.86 21.03,25.15 21.72,25.15 21.97,25.4 21.97,26.8 47.37,26.8 59.05,15.11 59.05,13.08 52.32,13.08 44.83,20.57 20.7,20.57
+1.8V_VDDVCO on BOTTOM: 22.53,19.1 27.05,23.62 50.67,23.62 55.27,19.02 76.12,19.02 76.12,15.24 52.32,15.24 47.62,19.94 28.83,19.94 25.76,16.87 25.76,12.7 22.53,12.7
+1.8V_VDDVCO on L10_PWR_SIG: 16.26,23.5 16.26,22.3 15.21,21.26 15.21,16.46 18.69,12.98 25.53,12.98 25.53,15.75 20.35,15.75 17.07,19.02 17.07,23.34 16.92,23.5
+3.3V on TOP: 113.79,17.91 111.51,17.91 111.51,11.23 113.13,11.23 113.13,12.09 113.36,12.32 113.79,12.32
+3.3V on TOP: 103.68,34.54 103.68,33.12 107.7,33.12 107.7,34.54
+3.3V on L10_PWR_SIG: 111.76,12.34 111.76,27.94 107.54,32.16 103.5,32.16 103.5,35.33 110.08,35.33 116.08,29.34 116.08,12.34
+3.3V_LMX on TOP: 72.42,44.81 73.79,44.81 73.79,43.28 72.42,43.28
+3.3V_LMX on BOTTOM: 110.87,14.73 110.87,12.45 104.65,12.45 104.65,14.73
+3.3V_LMX on L10_PWR_SIG: 65.79,51.18 65.79,31.27 76.83,20.22 101.14,20.22 102.64,18.72 102.64,14.33 103.96,13 103.96,12.45 107.95,12.45 107.95,14.43 106.48,15.9 106.48,24.21 105.28,25.4 83.49,25.4 73.91,34.98 73.91,51.18
+3.3V_LMXRF on BOTTOM: 110.87,18.67 110.87,16.38 107.31,16.38 107.31,18.67
+3.3V_LMXRF on L10_PWR_SIG: 107.31,16.64 107.31,25.4 106.15,26.57 86.94,26.57 75.56,37.95 75.56,52.2 65.28,52.2 65.28,49.89 60.96,49.89 60.96,56.39 83.34,56.39 83.34,40.56 93.29,30.61 108.08,30.61 111.12,27.56 111.12,16.38 107.57,16.38
+3.3VCLK on TOP: 38.3,35.81 38.3,35.05 37.9,34.65 35.79,34.65 35.79,35.28 36.32,35.81
+3.3VCLK on TOP: 30.89,47.98 30.89,46.91 38.71,46.91 38.71,47.98
+3.3VCLK on TOP: 30.91,36.6 30.91,35.2 29.62,35.2 29.62,36.6
+3.3VCLK on TOP: 42.49,37.29 42.49,36.55 43.94,36.55 43.94,37.97 43.18,37.97
+3.3VCLK on TOP: 98.22,33.91 102.82,33.91 103.07,33.66 103.07,32.38 102.72,32.03 98.73,32.03 98.22,32.54
+3.3VCLK on TOP: 40.51,47.35 40.51,45.97 42.27,45.97 42.27,47.35
+3.3VCLK on BOTTOM: 98.22,32.13 103.05,32.13 103.05,34.04 98.22,34.04
+3.3VCLK on L3_PWR_SIG: 29.74,35.31 29.31,35.74 29.31,48.01 41.78,48.01 46.61,43.18 50.44,43.18 61.87,31.75 96.27,31.75 98.42,33.91 103.13,33.91 103.11,25.4 56.11,25.4 46.89,34.62 35.92,34.62 35.23,35.31
+5VIN on TOP: 117.35,3.43 117.35,7.09 121.23,7.09 121.23,3.43
+5VIN on TOP, BOTTOM: 110.24,46.99 111.63,46.99 111.63,44.32 110.24,44.32
+5VIN on L3_PWR_SIG: 91.85,7.34 91.85,11.84 92.3,12.29 104.14,12.29 104.14,18.41 102.87,18.41 102.87,13.44 97.79,13.44 97.79,23.88 104.14,23.88 104.14,38.1 109.22,43.18 109.22,46.35 110.11,47.24 113.87,47.24 113.87,40.21 110.24,36.58 110.24,7.16 121.28,7.16 121.28,1.27 50.8,1.27 50.8,5.71 66.8,5.71 68.2,7.11 69.34,7.11 70.71,5.74 103.12,5.74 103.12,7.34
+5VIN_ADC on TOP: 118.75,15.11 118.75,17.58 122.43,17.58 122.43,14.02 119.84,14.02
+5VIN_ADC on L3_PWR_SIG: 116.84,19.05 116.84,35.56 121.28,35.56 121.28,24.21 123.57,24.21 123.57,35.56 128.27,35.56 128.27,24.21 131.44,24.21 131.44,35.56 135.89,35.56 135.89,20.7 134.01,18.82 125.5,18.82 122.56,15.88 122.56,13.97 119.89,13.97 118.75,15.11 118.75,17.14
+5VIN_CLK on TOP: 113.92,7.75 113.92,9.65 116.71,9.65 117.6,10.54 119.89,10.54 120.14,10.79 120.14,11.3 121.79,11.3 121.79,8.26 121.28,7.75
+5VIN_CLK on TOP: 111.76,38.61 111.76,35.2 113.28,35.2 113.28,38.61
+5VIN_CLK on BOTTOM: 111.38,35.18 111.38,38.1 112.14,38.1 112.14,38.86 113.28,38.86 113.41,38.99 113.41,39.37 114.68,39.37 114.68,37.97 113.28,36.58 113.28,35.18
+5VIN_CLK on L3_PWR_SIG: 111.12,36.7 113.16,38.73 114.3,38.73 116.08,36.96 116.08,18.34 117.98,16.43 117.98,15.37 121.92,11.43 121.92,7.62 116.26,7.62 116.26,12.01 113.67,14.61 113.67,14.58 110.87,17.37 110.87,25.53 111.12,25.78
-1.8V on BOTTOM: 39.47,1.63 39.47,3.35 42.49,3.35 42.67,3.17 43.31,3.17 43.31,2.16 42.8,2.16 42.42,1.78 42.42,1.63
-1.8V_VEE on TOP: 33.53,1.78 33.53,3.56 28.37,3.56 28.37,1.78
-1.8V_VEE on BOTTOM: 33.53,1.78 33.53,3.56 27.94,3.56 27.94,1.78
-1.8V_VEE on L10_PWR_SIG: 15.19,30.76 16.08,29.87 16.08,27.38 14.81,26.11 14.81,25.02 14.73,24.94 14.73,23.88 14.86,23.75 15.62,23.75 16,23.37 16,22.48 15.85,22.33 14.53,22.33 14.02,21.82 14.02,16.1 18.29,11.84 24.87,11.84 33.66,3.05 33.66,1.91 28.35,1.91 22.63,7.62 15.49,7.62 8.46,14.66 8.46,27.25 11.96,30.76
AVDD1.9V on TOP: 115.04,50.29 115.04,48.26 120.14,48.26 120.14,50.29
AVDD1.9V on L10_PWR_SIG: 106.43,57.4 45.97,57.4 40.64,52.07 29.95,52.07 29.95,64.52 109.73,64.52 120.02,54.23 120.02,48.39 115.44,48.39
AVDD1.15V on TOP: 127.53,50.16 127.53,47.88 133.5,47.88 133.5,49.54 132.88,50.16
AVDD1.15V on L3_PWR_SIG: 127.64,48.26 127.64,52.7 117.86,62.48 42.55,62.48 40.13,64.9 36.7,64.9 36.45,64.64 36.45,52.45 35.69,51.69 27.43,51.69 27.43,67.72 120.88,67.72 133.6,54.99 133.6,48.26
DVDD1.15V on TOP: 121.28,50.29 121.28,48.26 126.24,48.26 126.24,50.29
DVDD1.15V on L3_PWR_SIG: 121.28,48.26 121.28,49.53 114.94,55.88 48.26,55.88 44.7,52.32 43.94,52.32 43.92,52.3 43.92,52.32 36.7,52.32 36.7,64.26 36.96,64.52 39.62,64.52 42.29,61.85 116.97,61.85 126.49,52.32 126.49,48.26
DVDD_1P0V on TOP: 38.86,18.29 38.86,15.49 36.2,15.49 36.2,11.43 33.91,11.43 33.91,15.49 28.45,15.49 28.45,18.29
DVDD_1P0V on BOTTOM: 33.27,18.29 33.27,16.64 28.45,16.64 28.45,18.11 28.63,18.29
DVDD_1P0V on L3_PWR_SIG: 17.69,22.26 19.56,24.13 19.56,24.89 19.74,25.07 20.78,25.07 23.37,22.48 28.83,22.48 33.25,18.06 33.25,15.37 22.73,15.37 19,19.1 19,20.95
GND on TOP: 0.36,0.38 0.36,68.2 157.07,68.2 157.07,0.38 ; 14 cut-outs
GND on BOTTOM: 0.36,0.38 0.36,68.2 157.07,68.2 157.07,0.38 ; 3 cut-outs
GND on L2_GND, L3_PWR_SIG, L4_SIG, L5_GND, L6_SIG, L7_GND, L8_SIG, L9_GND, L10_PWR_SIG, L11_GND: 0.36,0.38 0.36,68.2 157.07,68.2 157.07,0.38 ; 1 cut-out
1P0V on TOP: 49.4,14.76 49.4,9.65 48.69,8.94 38.1,8.94 38.1,6.58 50.29,6.58 51.94,8.23 51.94,14.76
1P8V on BOTTOM: 74.32,7.75 74.32,8.99 73.63,9.68 60.45,9.68 60.45,14.73 64.77,14.73 64.77,12.7 68.38,12.7 68.38,14.35 71.7,14.35 71.7,13 72.24,12.47 75.92,12.47 77.06,11.33 77.06,10.39 77.8,9.65 82.93,9.65 83.44,9.14 83.44,7.14 74.93,7.14
1P8V on BOTTOM: 32.38,9.14 32.38,11.05 36.07,11.05 36.07,9.14
1P8V on L4_SIG: 32.38,8.13 32.38,10.92 35.94,10.92 35.94,10.54 37.06,9.42 60.6,9.42 64.01,12.83 76.92,12.83 76.92,7.37 67.82,7.37 66.55,6.1 34.42,6.1
+1P0V_ANA on TOP: 48.77,14.73 48.77,13.08 42.8,13.08 42.8,14.73
+1P0V_ANA on BOTTOM: 48.01,14.73 48.01,13.08 42.8,13.08 42.8,14.73
+1P0V_ANA on L3_PWR_SIG: 14.86,23.62 14.86,24.16 15.37,24.66 15.37,25.91 13.34,27.94 13.34,32.51 15.75,34.92 32.77,34.92 48.01,19.68 48.01,13.21 42.93,13.21 42.93,19.56 30.73,31.75 17.14,31.75 16.38,30.99 16.38,23.62
+1P0V_CLK on TOP, BOTTOM: 36.58,6.35 36.58,8.26 29.77,8.26 29.77,6.35
+1P0V_CLK on L10_PWR_SIG: 31.34,6.76 31.17,6.93 31.17,15.19 29.84,16.51 20.35,16.51 17.35,19.51 17.35,23.5 17.22,23.62 15.62,23.62 15.47,23.77 15.47,25.73 15.65,25.91 16.89,25.91 16.89,24.77 17.14,24.51 18.54,24.51 19.56,23.5 19.56,21.21 20.55,20.22 33.76,20.22 35.89,18.08 35.89,6.76
+1P0V_DIG on TOP: 48.64,9.78 48.64,11.35 44.75,11.35 44.58,11.18 36.7,11.18 36.7,9.42 48.29,9.42
+1P0V_DIG on BOTTOM: 43.69,9.53 43.69,11.18 38.23,11.18 38.23,9.53
+1P0V_DIG on L3_PWR_SIG: 33.55,15.24 33.55,18.44 26.59,25.4 19.68,25.4 19.3,25.02 19.3,24.64 18.41,23.75 18.03,23.75 18.03,25.78 18.92,26.92 20.32,28.57 28.45,28.57 36.32,20.7 36.32,11.18 43.69,11.18 43.69,8.13 32.89,8.13 32.89,14.58
+1P0V_VDDL1 on TOP, BOTTOM: 36.68,11.43 36.68,15.01 38,15.01 38,11.43
+1P0V_VDDL1 on L3_PWR_SIG: 36.7,11.56 36.7,20.95 28.83,28.83 20.07,28.83 18.29,26.8 17.7,26.14 17.7,24.38 16.89,24.38 16.89,29.77 18.36,31.24 30.73,31.24 40.64,21.34 40.64,11.56
+1P0V_VDDL1 on L10_PWR_SIG: 17.14,24.89 17.14,27.61 18.21,28.68 21.72,28.68 21.72,25.4 21.08,25.4 20.29,26.19 19.58,26.19 19.05,25.65 19.05,25.02 18.67,24.64 17.4,24.64
N16791900 on TOP: 104.09,46.07 104.09,47.31 102.64,47.31 102.64,48.1 104.92,48.1 104.92,46.07
N18967863 on BOTTOM: 34.42,1.65 34.42,3.3 36.96,3.3 36.96,1.65
N19083364 on L10_PWR_SIG: 31.34,41.78 31.34,44.2 32.49,45.34 41.38,45.34 41.38,43.43 39.73,41.78
N19083508 on TOP: 40.21,37.47 40.21,38.3 41,38.3 41.66,38.96 41.66,42.55 43.21,42.55 43.21,38.35 42.85,38.35 41.96,37.47
N19909006 on TOP: 88.9,15.75 88.9,14.1 92.84,14.1 92.84,14.86 92.2,14.86 91.31,15.75
N20122077 on TOP: 96.49,14.22 96.49,15.93 94.61,15.93 94.61,17.14 94.23,17.53 94.23,19.18 97.92,19.18 99.49,17.6 99.49,14.22
N20123661 on BOTTOM: 84.12,10.26 84.81,10.95 88.29,10.95 88.72,10.52 88.72,10.06 88.09,10.06 87.81,9.78 86.36,9.78 85.7,9.12 84.12,9.12
N20123671 on BOTTOM: 90.12,5.99 90.12,7.32 90.5,7.7 90.5,9.17 95.33,9.17 95.33,5.99
N20123815 on BOTTOM: 82.12,6.76 82.12,5.49 85.8,5.49 85.8,6.76
N20275378 on TOP: 115.04,47.52 115.04,46.1 118.72,46.1 118.72,47.52
N20275382 on TOP: 116.33,41.71 116.33,42.72 115.06,42.72 115.06,44.15 118.34,44.15 118.34,42.57 118.03,42.57 118.03,41.71
N20275455 on TOP: 116.89,36.63 116.89,38.66 118.9,38.66 118.9,39.75 122.1,39.75 122.1,36.63
N20275808 on TOP: 131.17,41.78 131.17,42.67 129.9,42.67 129.9,43.81 133.15,43.81 133.15,42.29 132.87,42.29 132.87,41.78
N20275812 on TOP: 131.72,36.7 131.72,38.68 133.76,38.68 133.76,39.67 136.91,39.67 136.91,36.7
N20276430 on TOP: 123.7,41.81 123.7,42.75 122.45,42.75 122.45,43.99 125.7,43.99 125.7,42.34 125.35,42.34 125.35,41.81
N20276536 on TOP: 122.15,47.47 122.15,46.08 126.26,46.08 126.26,47.47
N20276599 on TOP: 124.23,36.73 124.23,38.73 126.29,38.73 126.29,39.78 129.44,39.78 129.44,36.73
N20276940 on TOP: 129.79,47.37 129.79,46.05 133.65,46.05 133.65,47.37
N20285160 on TOP: 103.73,38.84 103.73,37.47 104.09,37.11 108.58,37.11 108.58,38.56 108.31,38.84
N20285160 on BOTTOM: 103.81,38.84 103.81,37.24 107.31,37.24 107.54,37.01 109.17,37.01 109.17,38.1 108.43,38.84
N20285833 on TOP: 124.71,6.1 128.65,6.1 128.63,9.51 127.65,9.51 127.25,9.91 127.25,16.26 122.94,16.26 122.94,7.8 122.56,7.42 122.56,5.08 123.7,5.08
N20285833 on BOTTOM: 124.84,6.1 128.65,6.1 128.65,9.53 127.51,9.53 127.38,9.65 127.38,16.26 122.68,16.26 122.68,5.84 124.59,5.84
N20426573 on BOTTOM: 44.58,2.41 44.58,3.25 46.71,3.25 47.4,3.94 47.4,4.9 49.56,4.9 49.56,1.35 45.64,1.35
N20484075 on TOP: 101.47,37.21 101.47,35.51 105.03,35.51 105.03,37.21
N20730230 on TOP: 71.63,7.62 71.63,9.35 65.79,9.35 65.79,11.13 73.79,11.13 73.79,7.62
N20730294 on TOP: 57.53,11.05 65.15,11.05 65.15,9.86 64.26,9.86 64.14,9.73 64.14,9.35 57.53,9.35
N20804074 on TOP: 82.68,15.24 39.37,15.24 39.37,18.84 84.41,18.84 86.49,16.76 86.49,13.46 84.45,13.46
N20825969 on TOP: 55.04,10.97 55.04,6.96 52.43,6.96 52.43,10.97

Small or netless copper shapes (teardrops, artwork), in the pictures only: 6 on TOP

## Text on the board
BOTTOM: LAYER 12 (BOTTOM SIDE)
Board Geometry/Soldermask Bottom: SOLDERMASK BOTTOM
Ref Des/Silkscreen Bottom: SILKSCREEN BOTTOM
User.Comments: C33 | C34 | C45 | C44 | C46 | C35 | C86 | C106 | C58 | C62 | C61 | C53 | C54 | C65 | C66 | C70 | A6 | A11 | A16 | A21 | A26 | A31 | A36 | C57 | C85 | C108 | C109 | HS2 | Q4 | U25 | U14 | U26 | U23 | U19 | For evaluation only; | not FCC approved for resale. | * | U5 | Y1 | U15 | U24 | C267 | C266 | F1 | R209 | R202 | C381 | FB41 | R203 | C274 | C437 | C377 | C168 | FB38 | C358 | R219 | FB13 | U22 | R235 | R220 | R173 | C270 | C269 | R137 | R222 | C354 | C353 | FB20 | C296 | C346 | C347 | C320 | U10 | C313 | R254 | C317 | C260 | R179 | R177 | C261 | R175 | R216 | R215 | C424 | R185 | R214 | R213 | C423 | R187 | R68 | R70 | R38 | R39 | C139 | R186 | R58 | R59 | R184 | R241 | R49 | R183 | R113 | R107 | C227 | C220 | C230 | C231 | C228 | C221 | C383 | C384 | R111 | C293 | C290 | C291 | C204 | R169 | C206 | U7 | R110 | R244 | C282 | R105 | R95 | R217 | R94 | R106 | C283 | R117 | R218 | R102 | R101 | R240 | C97 | R119 | C289 | R103 | C288 | R100 | C199 | C201 | R75 | R74 | R85 | R86 | C196 | C197 | C32 | C154 | R239 | C82 | C78 | C77 | C81 | C104 | FB42 | C184 | C181 | C100 | C99 | C91 | C50 | C92 | C107 | C69 | C74 | R138 | R139 | R211 | R142 | R206 | R205 | C275 | FB40 | C276 | R136 | C252 | R160 | C254 | C256 | C343 | C344 | R171 | FB43 | R238 | C318 | R355 | R256 | C324 | R182 | R354 | C326 | C325 | C316 | C51 | C314 | C63 | R246 | C309 | C308 | FB29 | C93 | C334 | C335 | C59 | C192 | C193 | C339 | C89 | C194 | C338 | R69 | C48 | R247 | FB31 | C333 | C170 | C336 | R47 | C332 | C337 | C171 | C95 | FB21 | C98 | C328 | C79 | R108 | R114 | C329 | C67 | FB23 | C28 | R30 | C101 | R243 | R112 | R104 | FB22 | R245 | R116 | FB27 | R109 | C83 | R242 | R121 | R120 | C229 | C223 | FB25 | R93 | C71 | C224 | R234 | C226 | C198 | R76 | R50 | C208 | C216 | C207 | C217 | C121 | C120 | C146 | R115 | FB17 | C279 | C119 | R118 | C114 | R99 | R96 | C115 | C143 | FB24 | C116 | R78 | R77 | C30 | C76 | R79 | R80 | C31 | R71 | R72 | R89 | R90 | C75 | R82 | R81 | C36 | C43 | C157 | R199 | R200 | C362 | U11 | FB44 | R338 | R339 | C281 | R207 | R62 | C178 | R61 | C49 | R331 | C96 | C88 | C103 | C73 | C105 | A1 | B1 | C1 | D1 | E1 | G1 | H1 | J1 | K1 | A40 | B40 | C40 | D40 | E40 | F40 | G40 | H40 | J40 | K40 | K36 | K6 | K31 | K11 | K16 | K21 | K26 | R341 | C438 | R342 | C439 | (8 PL) | ALPHANOVATECH # | PUSH PIN | 2 EA | NR35-25B-IP3N | J14 | TEXAS INSTRUMENTS, INC. | TSW40RF80EVM  PCB REV D | 15. DIFFERENTIAL PAIRS WITH 5MIL TRACE WIDTH AND 12MIL SPACING ON LAYER 6 AND LAYER 8 SHALL BE 100 OHMS DIFFERENTIAL +/- 10%. | TOP VIEW | BOTTOM VIEW
TOP: LAYER 1 (TOP SIDE)
Board Geometry/Soldermask Top: SOLDERMASK TOP
Ref Des/Silkscreen Top: OUT | JP3 | JP7 | CLKOUT | EXT | CLK | UL94V-0 | TSW40RF80EVM | PCB REV D | SILKSCREEN TOP
L2_GND: LAYER 2 - GND
L3_PWR_SIG: LAYER 3 - POWER
L4_SIG: LAYER 4 - SIGNAL
L5_GND: LAYER 5 - GROUND
L6_SIG: LAYER 6 - SIGNAL
L7_GND: LAYER 7 - GROUND
L8_SIG: LAYER 8 - SIGNAL
L9_GND: LAYER 9 - GROUND
L10_PWR_SIG: LAYER 10 - POWER/SIGNAL
L11_GND: LAYER 11 - GROUND
PLACE_BOUND_TOP: PASTEMASK TOP
DISPLAY_TOP: PASTEMASK BOTTOM
User.6: SOLDERMASK TOP SOCKET BOARD
User.7: PASTEMASK TOP SOCKET BOARD
User.11: MEGTRON 6
User.12: 3. MARK BOARD'S SILKSCREEN AND ESD BAG WITH THE APPROPREATE EVM PART NUMBER. | 5. FAN-SINK HS2 SOLDERED TO BOTTOM SIDE OF BOARD, UNDERNEATH U2.  MAKE SURE FAN BLOW INWARD ACCROSS PCB. | 4. HEATSINK HS1 INSTALLED ON TOP SIDE WITH SPRING LOADED PINS, REFER TO SPEC DRAWING FOR INSTALLATION REFERENCE. | 6. IPC-A-610 / ACCEPTABILITY OF ELECTRONIC ASSEMBLIES, CLASS 2, CURRENT REVISION.
User.24: FIGURE | SIZE | 5.0 | 6.0 | 8.0 | 10.0 | 12.0 | 15.0 | 32.0 | 38.0 | 40.0 | 62.0 | 67.0 | 106.0 | 125.0 | 50.0 | 104.0x35.0 | 118.11x39.37 | 137.8x39.37 | DRILL CHART: TOP to BOTTOM | ALL UNITS ARE IN MILS | PLATED | NON-PLATED | QTY | 2 | 1357 | 44 | 145 | 2430 | 74 | 263 | 11 | 28 | 9 | 10 | 3 | 4 | 5 | 1
